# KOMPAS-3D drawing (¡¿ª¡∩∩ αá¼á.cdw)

Views: Спереди 1, Спереди, Проекционный вид 2, Проекционный вид 3
Referenced files in D:\SERG\ВЕРТОЛЁТЫ\мануалы на вертолёты\Рама Фьюжена\под резку проволокой\: bottom base.m3d
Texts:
  СЕРГЕЙ
  Д16  ГОСТ 4784-97
Dimensions and other numbers on the sheet: 1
